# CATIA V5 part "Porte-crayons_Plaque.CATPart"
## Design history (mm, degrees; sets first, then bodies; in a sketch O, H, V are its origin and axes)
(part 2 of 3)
    line L795 (29.2957, 73.0276) -> (29.2344, 72.9847)
    line L796 (29.3535, 73.0745) -> (29.2957, 73.0276)
    line L797 (29.4075, 73.1251) -> (29.3535, 73.0745)
    line L798 (29.4578, 73.1794) -> (29.4075, 73.1251)
    line L799 (29.5043, 73.2373) -> (29.4578, 73.1794)
    line L800 (29.547, 73.2989) -> (29.5043, 73.2373)
    line L801 (29.586, 73.3642) -> (29.547, 73.2989)
    line L802 (29.6213, 73.4331) -> (29.586, 73.3642)
    line L803 (29.6527, 73.5057) -> (29.6213, 73.4331)
    line L804 (29.6804, 73.5819) -> (29.6527, 73.5057)
    line L805 (29.7043, 73.6618) -> (29.6804, 73.5819)
    line L806 (29.2381, 73.7194) -> (29.7043, 73.6618)
    line L807 (24.4786, 72.5574) -> (24.4776, 72.6415)
    line L808 (24.4857, 72.4777) -> (24.4786, 72.5574)
    line L809 (24.4989, 72.4023) -> (24.4857, 72.4777)
    line L810 (24.5181, 72.3313) -> (24.4989, 72.4023)
    line L811 (24.5434, 72.2645) -> (24.5181, 72.3313)
    line L812 (24.5748, 72.2022) -> (24.5434, 72.2645)
    line L813 (24.6122, 72.1441) -> (24.5748, 72.2022)
    line L814 (24.6557, 72.0904) -> (24.6122, 72.1441)
    line L815 (24.7053, 72.041) -> (24.6557, 72.0904)
    line L816 (24.7609, 71.996) -> (24.7053, 72.041)
    line L817 (24.8214, 71.9553) -> (24.7609, 71.996)
    line L818 (24.8855, 71.9188) -> (24.8214, 71.9553)
    line L819 (24.9533, 71.8867) -> (24.8855, 71.9188)
    line L820 (25.0248, 71.8588) -> (24.9533, 71.8867)
    line L821 (25.0999, 71.8352) -> (25.0248, 71.8588)
    line L822 (25.1787, 71.816) -> (25.0999, 71.8352)
    line L823 (25.2612, 71.801) -> (25.1787, 71.816)
    line L824 (25.3473, 71.7902) -> (25.2612, 71.801)
    line L825 (25.4371, 71.7838) -> (25.3473, 71.7902)
    line L826 (25.5305, 71.7817) -> (25.4371, 71.7838)
    line L827 (25.6094, 71.7832) -> (25.5305, 71.7817)
    line L828 (25.6859, 71.7877) -> (25.6094, 71.7832)
    line L829 (25.7597, 71.7952) -> (25.6859, 71.7877)
    line L830 (25.8311, 71.8057) -> (25.7597, 71.7952)
    line L831 (25.8999, 71.8193) -> (25.8311, 71.8057)
    line L832 (25.9662, 71.8358) -> (25.8999, 71.8193)
    line L833 (26.03, 71.8554) -> (25.9662, 71.8358)
    line L834 (26.0912, 71.8779) -> (26.03, 71.8554)
    line L835 (26.1499, 71.9035) -> (26.0912, 71.8779)
    line L836 (26.2061, 71.9321) -> (26.1499, 71.9035)
    line L837 (26.2595, 71.9633) -> (26.2061, 71.9321)
    line L838 (26.3099, 71.9966) -> (26.2595, 71.9633)
    line L839 (26.3575, 72.0321) -> (26.3099, 71.9966)
    line L840 (26.402, 72.0698) -> (26.3575, 72.0321)
    line L841 (26.4436, 72.1097) -> (26.402, 72.0698)
    line L842 (26.4822, 72.1518) -> (26.4436, 72.1097)
    line L843 (26.5179, 72.1961) -> (26.4822, 72.1518)
    line L844 (26.5506, 72.2425) -> (26.5179, 72.1961)
    line L845 (26.5804, 72.2911) -> (26.5506, 72.2425)
    line L846 (26.6072, 72.3419) -> (26.5804, 72.2911)
    line L847 (26.6312, 72.3975) -> (26.6072, 72.3419)
    line L848 (26.6527, 72.4602) -> (26.6312, 72.3975)
    line L849 (26.6717, 72.5302) -> (26.6527, 72.4602)
    line L850 (26.6882, 72.6075) -> (26.6717, 72.5302)
    line L851 (26.7021, 72.692) -> (26.6882, 72.6075)
    line L852 (26.7135, 72.7837) -> (26.7021, 72.692)
    line L853 (26.7224, 72.8827) -> (26.7135, 72.7837)
    line L854 (26.7287, 72.9889) -> (26.7224, 72.8827)
    line L855 (26.7325, 73.1024) -> (26.7287, 72.9889)
    line L856 (26.7338, 73.2231) -> (26.7325, 73.1024)
    line L857 (26.7338, 75.5244) -> (26.7338, 73.2231)
    line L858 (26.3176, 75.5244) -> (26.7338, 75.5244)
    line L859 (26.3176, 75.2035) -> (26.3176, 75.5244)
    line L860 (26.2548, 75.2759) -> (26.3176, 75.2035)
    line L861 (26.1887, 75.3406) -> (26.2548, 75.2759)
    line L862 (26.1192, 75.3978) -> (26.1887, 75.3406)
    line L863 (26.0465, 75.4473) -> (26.1192, 75.3978)
    line L864 (25.9704, 75.4893) -> (26.0465, 75.4473)
    line L865 (25.8911, 75.5236) -> (25.9704, 75.4893)
    line L866 (25.8084, 75.5502) -> (25.8911, 75.5236)
    line L867 (25.7224, 75.5693) -> (25.8084, 75.5502)
    line L868 (25.6331, 75.5807) -> (25.7224, 75.5693)
    line L869 (25.5405, 75.5845) -> (25.6331, 75.5807)
    line L870 (25.4707, 75.5828) -> (25.5405, 75.5845)
    line L871 (25.4028, 75.5775) -> (25.4707, 75.5828)
    line L872 (25.3367, 75.5687) -> (25.4028, 75.5775)
    line L873 (25.2724, 75.5564) -> (25.3367, 75.5687)
    line L874 (25.2099, 75.5407) -> (25.2724, 75.5564)
    line L875 (25.1493, 75.5214) -> (25.2099, 75.5407)
    line L876 (25.0905, 75.4985) -> (25.1493, 75.5214)
    line L877 (25.0335, 75.4722) -> (25.0905, 75.4985)
    line L878 (24.9784, 75.4424) -> (25.0335, 75.4722)
    line L879 (24.9251, 75.409) -> (24.9784, 75.4424)
    line L880 (24.8739, 75.3725) -> (24.9251, 75.409)
    line L881 (24.8253, 75.333) -> (24.8739, 75.3725)
    line L882 (24.7791, 75.2906) -> (24.8253, 75.333)
    line L883 (24.7354, 75.2452) -> (24.7791, 75.2906)
    line L884 (24.6942, 75.1969) -> (24.7354, 75.2452)
    line L885 (24.6554, 75.1457) -> (24.6942, 75.1969)
    line L886 (24.6192, 75.0915) -> (24.6554, 75.1457)
    line L887 (24.5854, 75.0344) -> (24.6192, 75.0915)
    line L888 (24.5541, 74.9744) -> (24.5854, 75.0344)
    line L889 (24.5252, 74.9114) -> (24.5541, 74.9744)
    line L890 (24.4991, 74.8464) -> (24.5252, 74.9114)
    line L891 (24.4756, 74.7802) -> (24.4991, 74.8464)
    line L892 (24.4549, 74.7129) -> (24.4756, 74.7802)
    line L893 (24.437, 74.6443) -> (24.4549, 74.7129)
    line L894 (24.4218, 74.5746) -> (24.437, 74.6443)
    line L895 (24.4094, 74.5037) -> (24.4218, 74.5746)
    line L896 (24.3998, 74.4316) -> (24.4094, 74.5037)
    line L897 (24.3929, 74.3583) -> (24.3998, 74.4316)
    line L898 (24.3888, 74.2839) -> (24.3929, 74.3583)
    line L899 (24.3874, 74.2083) -> (24.3888, 74.2839)
    line L900 (24.3904, 74.099) -> (24.3874, 74.2083)
    line L901 (24.3994, 73.993) -> (24.3904, 74.099)
    line L902 (24.4144, 73.8901) -> (24.3994, 73.993)
    line L903 (24.4355, 73.7903) -> (24.4144, 73.8901)
    line L904 (24.4626, 73.6938) -> (24.4355, 73.7903)
    line L905 (24.4957, 73.6003) -> (24.4626, 73.6938)
    line L906 (24.5348, 73.51) -> (24.4957, 73.6003)
    line L907 (24.5799, 73.4229) -> (24.5348, 73.51)
    line L908 (24.631, 73.339) -> (24.5799, 73.4229)
    line L909 (24.6882, 73.2582) -> (24.631, 73.339)
    line L910 (24.7509, 73.1829) -> (24.6882, 73.2582)
    line L911 (24.8184, 73.1156) -> (24.7509, 73.1829)
    line L912 (24.891, 73.0562) -> (24.8184, 73.1156)
    line L913 (24.9685, 73.0047) -> (24.891, 73.0562)
    line L914 (25.0511, 72.9611) -> (24.9685, 73.0047)
    line L915 (25.1385, 72.9255) -> (25.0511, 72.9611)
    line L916 (25.2309, 72.8978) -> (25.1385, 72.9255)
    line L917 (25.3283, 72.8779) -> (25.2309, 72.8978)
    line L918 (25.4307, 72.8661) -> (25.3283, 72.8779)
    line L919 (25.538, 72.8621) -> (25.4307, 72.8661)
    line L920 (25.6248, 72.8656) -> (25.538, 72.8621)
    line L921 (25.7087, 72.876) -> (25.6248, 72.8656)
    line L922 (25.7896, 72.8935) -> (25.7087, 72.876)
    line L923 (25.8677, 72.9179) -> (25.7896, 72.8935)
    line L924 (25.9429, 72.9492) -> (25.8677, 72.9179)
    line L925 (26.0151, 72.9875) -> (25.9429, 72.9492)
    line L926 (26.0844, 73.0329) -> (26.0151, 72.9875)
    line L927 (26.1509, 73.0851) -> (26.0844, 73.0329)
    line L928 (26.2144, 73.1443) -> (26.1509, 73.0851)
    line L929 (26.275, 73.2105) -> (26.2144, 73.1443)
    line L930 (26.2751, 73.1253) -> (26.275, 73.2105)
    line L931 (26.2745, 73.0462) -> (26.2751, 73.1253)
    line L932 (26.2731, 72.9731) -> (26.2745, 73.0462)
    line L933 (26.271, 72.9061) -> (26.2731, 72.9731)
    line L934 (26.2681, 72.8452) -> (26.271, 72.9061)
    line L935 (26.2645, 72.7903) -> (26.2681, 72.8452)
    line L936 (26.2601, 72.7415) -> (26.2645, 72.7903)
    line L937 (26.2549, 72.6988) -> (26.2601, 72.7415)
    line L938 (26.2491, 72.6621) -> (26.2549, 72.6988)
    line L939 (26.2424, 72.6315) -> (26.2491, 72.6621)
    line L940 (26.2293, 72.5874) -> (26.2424, 72.6315)
    line L941 (26.214, 72.5452) -> (26.2293, 72.5874)
    line L942 (26.1964, 72.5051) -> (26.214, 72.5452)
    line L943 (26.1766, 72.467) -> (26.1964, 72.5051)
    line L944 (26.1547, 72.4309) -> (26.1766, 72.467)
    line L945 (26.1305, 72.3968) -> (26.1547, 72.4309)
    line L946 (26.1042, 72.3648) -> (26.1305, 72.3968)
    line L947 (26.0756, 72.3347) -> (26.1042, 72.3648)
    line L948 (26.0448, 72.3066) -> (26.0756, 72.3347)
    line L949 (26.0118, 72.2805) -> (26.0448, 72.3066)
    line L950 (25.9763, 72.2567) -> (26.0118, 72.2805)
    line L951 (25.9379, 72.2354) -> (25.9763, 72.2567)
    line L952 (25.8967, 72.2166) -> (25.9379, 72.2354)
    line L953 (25.8525, 72.2003) -> (25.8967, 72.2166)
    line L954 (25.8056, 72.1865) -> (25.8525, 72.2003)
    line L955 (25.7558, 72.1752) -> (25.8056, 72.1865)
    line L956 (25.7031, 72.1665) -> (25.7558, 72.1752)
    line L957 (25.6476, 72.1602) -> (25.7031, 72.1665)
    line L958 (25.5892, 72.1564) -> (25.6476, 72.1602)
    line L959 (25.528, 72.1552) -> (25.5892, 72.1564)
    line L960 (25.4711, 72.1564) -> (25.528, 72.1552)
    line L961 (25.4166, 72.1602) -> (25.4711, 72.1564)
    line L962 (25.3646, 72.1665) -> (25.4166, 72.1602)
    line L963 (25.315, 72.1752) -> (25.3646, 72.1665)
    line L964 (25.2679, 72.1865) -> (25.315, 72.1752)
    line L965 (25.2232, 72.2003) -> (25.2679, 72.1865)
    line L966 (25.1811, 72.2166) -> (25.2232, 72.2003)
    line L967 (25.1413, 72.2354) -> (25.1811, 72.2166)
    line L968 (25.104, 72.2567) -> (25.1413, 72.2354)
    line L969 (25.0692, 72.2805) -> (25.104, 72.2567)
    line L970 (25.0451, 72.3002) -> (25.0692, 72.2805)
    line L971 (25.023, 72.322) -> (25.0451, 72.3002)
    line L972 (25.0028, 72.3461) -> (25.023, 72.322)
    line L973 (24.9846, 72.3724) -> (25.0028, 72.3461)
    line L974 (24.9683, 72.4009) -> (24.9846, 72.3724)
    line L975 (24.954, 72.4315) -> (24.9683, 72.4009)
    line L976 (24.9417, 72.4644) -> (24.954, 72.4315)
    line L977 (24.9313, 72.4995) -> (24.9417, 72.4644)
    line L978 (24.9228, 72.5368) -> (24.9313, 72.4995)
    line L979 (24.9163, 72.5763) -> (24.9228, 72.5368)
    line L980 (24.4776, 72.6415) -> (24.9163, 72.5763)
    line L981 (21.5406, 74.0615) -> (21.5371, 74.1932)
    line L982 (21.5509, 73.9361) -> (21.5406, 74.0615)
    line L983 (21.5681, 73.8171) -> (21.5509, 73.9361)
    line L984 (21.5923, 73.7043) -> (21.5681, 73.8171)
    line L985 (21.6233, 73.5979) -> (21.5923, 73.7043)
    line L986 (21.6612, 73.4977) -> (21.6233, 73.5979)
    line L987 (21.706, 73.4039) -> (21.6612, 73.4977)
    line L988 (21.7577, 73.3165) -> (21.706, 73.4039)
    line L989 (21.8163, 73.2353) -> (21.7577, 73.3165)
    line L990 (21.8818, 73.1604) -> (21.8163, 73.2353)
    line L991 (21.9529, 73.0923) -> (21.8818, 73.1604)
    line L992 (22.0283, 73.0314) -> (21.9529, 73.0923)
    line L993 (22.1079, 72.9776) -> (22.0283, 73.0314)
    line L994 (22.1919, 72.931) -> (22.1079, 72.9776)
    line L995 (22.2801, 72.8916) -> (22.1919, 72.931)
    line L996 (22.3726, 72.8593) -> (22.2801, 72.8916)
    line L997 (22.4694, 72.8342) -> (22.3726, 72.8593)
    line L998 (22.5705, 72.8163) -> (22.4694, 72.8342)
    line L999 (22.6759, 72.8055) -> (22.5705, 72.8163)
    line L1000 (22.7855, 72.8019) -> (22.6759, 72.8055)
    line L1001 (22.8547, 72.8036) -> (22.7855, 72.8019)
    line L1002 (22.9227, 72.8085) -> (22.8547, 72.8036)
    line L1003 (22.9897, 72.8166) -> (22.9227, 72.8085)
    line L1004 (23.0557, 72.828) -> (22.9897, 72.8166)
    line L1005 (23.1205, 72.8427) -> (23.0557, 72.828)
    line L1006 (23.1842, 72.8606) -> (23.1205, 72.8427)
    line L1007 (23.2469, 72.8818) -> (23.1842, 72.8606)
    line L1008 (23.3086, 72.9062) -> (23.2469, 72.8818)
    line L1009 (23.3691, 72.9339) -> (23.3086, 72.9062)
    line L1010 (23.4285, 72.9649) -> (23.3691, 72.9339)
    line L1011 (23.486, 72.9988) -> (23.4285, 72.9649)
    line L1012 (23.5407, 73.0353) -> (23.486, 72.9988)
    line L1013 (23.5926, 73.0745) -> (23.5407, 73.0353)
    line L1014 (23.6417, 73.1163) -> (23.5926, 73.0745)
    line L1015 (23.688, 73.1607) -> (23.6417, 73.1163)
    line L1016 (23.7314, 73.2078) -> (23.688, 73.1607)
    line L1017 (23.7721, 73.2575) -> (23.7314, 73.2078)
    line L1018 (23.81, 73.3098) -> (23.7721, 73.2575)
    line L1019 (23.845, 73.3648) -> (23.81, 73.3098)
    line L1020 (23.8772, 73.4224) -> (23.845, 73.3648)
    line L1021 (23.9065, 73.4835) -> (23.8772, 73.4224)
    line L1022 (23.9327, 73.549) -> (23.9065, 73.4835)
    line L1023 (23.9559, 73.6189) -> (23.9327, 73.549)
    line L1024 (23.9759, 73.6931) -> (23.9559, 73.6189)
    line L1025 (23.9929, 73.7718) -> (23.9759, 73.6931)
    line L1026 (24.0067, 73.8548) -> (23.9929, 73.7718)
    line L1027 (24.0175, 73.9422) -> (24.0067, 73.8548)
    line L1028 (24.0252, 74.0341) -> (24.0175, 73.9422)
    line L1029 (24.0299, 74.1302) -> (24.0252, 74.0341)
    line L1030 (24.0314, 74.2308) -> (24.0299, 74.1302)
    line L1031 (24.0279, 74.3549) -> (24.0314, 74.2308)
    line L1032 (24.0175, 74.4735) -> (24.0279, 74.3549)
    line L1033 (24, 74.5867) -> (24.0175, 74.4735)
    line L1034 (23.9757, 74.6943) -> (24, 74.5867)
    line L1035 (23.9443, 74.7964) -> (23.9757, 74.6943)
    line L1036 (23.906, 74.8931) -> (23.9443, 74.7964)
    line L1037 (23.8607, 74.9842) -> (23.906, 74.8931)
    line L1038 (23.8084, 75.0699) -> (23.8607, 74.9842)
    line L1039 (23.7492, 75.1501) -> (23.8084, 75.0699)
    line L1040 (23.683, 75.2248) -> (23.7492, 75.1501)
    line L1041 (23.6113, 75.2931) -> (23.683, 75.2248)
    line L1042 (23.5356, 75.3543) -> (23.6113, 75.2931)
    line L1043 (23.4558, 75.4082) -> (23.5356, 75.3543)
    line L1044 (23.3721, 75.455) -> (23.4558, 75.4082)
    line L1045 (23.2844, 75.4946) -> (23.3721, 75.455)
    line L1046 (23.1926, 75.5269) -> (23.2844, 75.4946)
    line L1047 (23.0969, 75.5521) -> (23.1926, 75.5269)
    line L1048 (22.9971, 75.5701) -> (23.0969, 75.5521)
    line L1049 (22.8933, 75.5809) -> (22.9971, 75.5701)
    line L1050 (22.7855, 75.5845) -> (22.8933, 75.5809)
    line L1051 (22.6883, 75.5816) -> (22.7855, 75.5845)
    line L1052 (22.594, 75.5727) -> (22.6883, 75.5816)
    line L1053 (22.5027, 75.5579) -> (22.594, 75.5727)
    line L1054 (22.4145, 75.5372) -> (22.5027, 75.5579)
    line L1055 (22.3293, 75.5106) -> (22.4145, 75.5372)
    line L1056 (22.247, 75.478) -> (22.3293, 75.5106)
    line L1057 (22.1678, 75.4396) -> (22.247, 75.478)
    line L1058 (22.0916, 75.3952) -> (22.1678, 75.4396)
    line L1059 (22.0184, 75.3449) -> (22.0916, 75.3952)
    line L1060 (21.9482, 75.2887) -> (22.0184, 75.3449)
    line L1061 (21.8701, 75.2137) -> (21.9482, 75.2887)
    line L1062 (21.8002, 75.131) -> (21.8701, 75.2137)
    line L1063 (21.7386, 75.0406) -> (21.8002, 75.131)
    line L1064 (21.6851, 74.9426) -> (21.7386, 75.0406)
    line L1065 (21.6399, 74.8368) -> (21.6851, 74.9426)
    line L1066 (21.6029, 74.7235) -> (21.6399, 74.8368)
    line L1067 (21.5741, 74.6024) -> (21.6029, 74.7235)
    line L1068 (21.5536, 74.4737) -> (21.5741, 74.6024)
    line L1069 (21.5412, 74.3373) -> (21.5536, 74.4737)
    line L1070 (21.5371, 74.1932) -> (21.5412, 74.3373)
    line L1071 (17.8797, 72.8621) -> (17.4284, 72.8621)
    line L1072 (17.8797, 74.2434) -> (17.8797, 72.8621)
    line L1073 (17.8804, 74.3144) -> (17.8797, 74.2434)
    line L1074 (17.8826, 74.3819) -> (17.8804, 74.3144)
    line L1075 (17.8862, 74.4461) -> (17.8826, 74.3819)
    line L1076 (17.8913, 74.5069) -> (17.8862, 74.4461)
    line L1077 (17.8978, 74.5642) -> (17.8913, 74.5069)
    line L1078 (17.9058, 74.6182) -> (17.8978, 74.5642)
    line L1079 (17.9153, 74.6687) -> (17.9058, 74.6182)
    line L1080 (17.9262, 74.7159) -> (17.9153, 74.6687)
    line L1081 (17.9385, 74.7596) -> (17.9262, 74.7159)
    line L1082 (17.9523, 74.7999) -> (17.9385, 74.7596)
    line L1083 (17.9678, 74.8376) -> (17.9523, 74.7999)
    line L1084 (17.985, 74.8734) -> (17.9678, 74.8376)
    line L1085 (18.004, 74.9073) -> (17.985, 74.8734)
    line L1086 (18.0248, 74.9395) -> (18.004, 74.9073)
    line L1087 (18.0473, 74.9697) -> (18.0248, 74.9395)
    line L1088 (18.0716, 74.9981) -> (18.0473, 74.9697)
    line L1089 (18.0977, 75.0247) -> (18.0716, 74.9981)
    line L1090 (18.1256, 75.0494) -> (18.0977, 75.0247)
    line L1091 (18.1553, 75.0722) -> (18.1256, 75.0494)
    line L1092 (18.1867, 75.0932) -> (18.1553, 75.0722)
    line L1093 (18.2194, 75.1122) -> (18.1867, 75.0932)
    line L1094 (18.2526, 75.1293) -> (18.2194, 75.1122)
    line L1095 (18.2864, 75.1443) -> (18.2526, 75.1293)
    line L1096 (18.3207, 75.1573) -> (18.2864, 75.1443)
    line L1097 (18.3556, 75.1684) -> (18.3207, 75.1573)
    line L1098 (18.3912, 75.1774) -> (18.3556, 75.1684)
    line L1099 (18.4272, 75.1844) -> (18.3912, 75.1774)
    line L1100 (18.4639, 75.1894) -> (18.4272, 75.1844)
    line L1101 (18.5011, 75.1924) -> (18.4639, 75.1894)
    line L1102 (18.539, 75.1934) -> (18.5011, 75.1924)
    line L1103 (18.5877, 75.1919) -> (18.539, 75.1934)
    line L1104 (18.6336, 75.1874) -> (18.5877, 75.1919)
    line L1105 (18.6767, 75.1799) -> (18.6336, 75.1874)
    line L1106 (18.717, 75.1694) -> (18.6767, 75.1799)
    line L1107 (18.7545, 75.1558) -> (18.717, 75.1694)
    line L1108 (18.7892, 75.1393) -> (18.7545, 75.1558)
    line L1109 (18.8211, 75.1197) -> (18.7892, 75.1393)
    line L1110 (18.8502, 75.0972) -> (18.8211, 75.1197)
    line L1111 (18.8765, 75.0716) -> (18.8502, 75.0972)
    line L1112 (18.8999, 75.043) -> (18.8765, 75.0716)
    line L1113 (18.9209, 75.0115) -> (18.8999, 75.043)
    line L1114 (18.9397, 74.9769) -> (18.9209, 75.0115)
    line L1115 (18.9562, 74.9393) -> (18.9397, 74.9769)
    line L1116 (18.9705, 74.8986) -> (18.9562, 74.9393)
    line L1117 (18.9827, 74.855) -> (18.9705, 74.8986)
    line L1118 (18.9926, 74.8084) -> (18.9827, 74.855)
    line L1119 (19.0003, 74.7588) -> (18.9926, 74.8084)
    line L1120 (19.0058, 74.7061) -> (19.0003, 74.7588)
    line L1121 (19.0091, 74.6505) -> (19.0058, 74.7061)
    line L1122 (19.0102, 74.5918) -> (19.0091, 74.6505)
    line L1123 (19.0102, 72.8621) -> (19.0102, 74.5918)
    line L1124 (19.4615, 72.8621) -> (19.0102, 72.8621)
    line L1125 (19.4615, 74.4088) -> (19.4615, 72.8621)
    line L1126 (19.4633, 74.4888) -> (19.4615, 74.4088)
    line L1127 (19.4689, 74.5643) -> (19.4633, 74.4888)
    line L1128 (19.4782, 74.6353) -> (19.4689, 74.5643)
    line L1129 (19.4911, 74.7018) -> (19.4782, 74.6353)
    line L1130 (19.5079, 74.7638) -> (19.4911, 74.7018)
    line L1131 (19.5282, 74.8214) -> (19.5079, 74.7638)
    line L1132 (19.5524, 74.8745) -> (19.5282, 74.8214)
    line L1133 (19.5802, 74.923) -> (19.5524, 74.8745)
    line L1134 (19.6117, 74.9671) -> (19.5802, 74.923)
    line L1135 (19.647, 75.0067) -> (19.6117, 74.9671)
    line L1136 (19.685, 75.0422) -> (19.647, 75.0067)
    line L1137 (19.725, 75.0739) -> (19.685, 75.0422)
    line L1138 (19.7669, 75.1019) -> (19.725, 75.0739)
    line L1139 (19.8106, 75.1262) -> (19.7669, 75.1019)
    line L1140 (19.8563, 75.1468) -> (19.8106, 75.1262)
    line L1141 (19.9039, 75.1636) -> (19.8563, 75.1468)
    line L1142 (19.9534, 75.1766) -> (19.9039, 75.1636)
    line L1143 (20.0047, 75.186) -> (19.9534, 75.1766)
    line L1144 (20.058, 75.1916) -> (20.0047, 75.186)
    line L1145 (20.1132, 75.1934) -> (20.058, 75.1916)
    line L1146 (20.1439, 75.1927) -> (20.1132, 75.1934)
    line L1147 (20.1738, 75.1905) -> (20.1439, 75.1927)
    line L1148 (20.2029, 75.1869) -> (20.1738, 75.1905)
    line L1149 (20.2312, 75.1818) -> (20.2029, 75.1869)
    line L1150 (20.2586, 75.1753) -> (20.2312, 75.1818)
    line L1151 (20.2853, 75.1673) -> (20.2586, 75.1753)
    line L1152 (20.3112, 75.1578) -> (20.2853, 75.1673)
    line L1153 (20.3362, 75.1469) -> (20.3112, 75.1578)
    line L1154 (20.3605, 75.1346) -> (20.3362, 75.1469)
    line L1155 (20.384, 75.1208) -> (20.3605, 75.1346)
    line L1156 (20.4063, 75.1057) -> (20.384, 75.1208)
    line L1157 (20.4272, 75.0898) -> (20.4063, 75.1057)
    line L1158 (20.4468, 75.073) -> (20.4272, 75.0898)
    line L1159 (20.4648, 75.0552) -> (20.4468, 75.073)
    line L1160 (20.4814, 75.0365) -> (20.4648, 75.0552)
    line L1161 (20.4966, 75.0168) -> (20.4814, 75.0365)
    line L1162 (20.5104, 74.9962) -> (20.4966, 75.0168)
    line L1163 (20.5228, 74.9747) -> (20.5104, 74.9962)
    line L1164 (20.5337, 74.9523) -> (20.5228, 74.9747)
    line L1165 (20.5432, 74.929) -> (20.5337, 74.9523)
    line L1166 (20.5515, 74.9036) -> (20.5432, 74.929)
    line L1167 (20.5589, 74.8753) -> (20.5515, 74.9036)
    line L1168 (20.5655, 74.8439) -> (20.5589, 74.8753)
    line L1169 (20.5712, 74.8094) -> (20.5655, 74.8439)
    line L1170 (20.5761, 74.772) -> (20.5712, 74.8094)
    line L1171 (20.58, 74.7315) -> (20.5761, 74.772)
    line L1172 (20.5831, 74.688) -> (20.58, 74.7315)
    line L1173 (20.5853, 74.6414) -> (20.5831, 74.688)
    line L1174 (20.5866, 74.5918) -> (20.5853, 74.6414)
    line L1175 (20.587, 74.5392) -> (20.5866, 74.5918)
    line L1176 (20.587, 72.8621) -> (20.587, 74.5392)
    line L1177 (21.0358, 72.8621) -> (20.587, 72.8621)
    line L1178 (21.0358, 74.6896) -> (21.0358, 72.8621)
    line L1179 (21.0336, 74.7785) -> (21.0358, 74.6896)
    line L1180 (21.0272, 74.8626) -> (21.0336, 74.7785)
    line L1181 (21.0166, 74.942) -> (21.0272, 74.8626)
    line L1182 (21.0017, 75.0167) -> (21.0166, 74.942)
    line L1183 (20.9825, 75.0866) -> (21.0017, 75.0167)
    line L1184 (20.959, 75.1518) -> (20.9825, 75.0866)
    line L1185 (20.9313, 75.2122) -> (20.959, 75.1518)
    line L1186 (20.8994, 75.2679) -> (20.9313, 75.2122)
    line L1187 (20.8632, 75.3189) -> (20.8994, 75.2679)
    line L1188 (20.8227, 75.3652) -> (20.8632, 75.3189)
    line L1189 (20.7782, 75.4068) -> (20.8227, 75.3652)
    line L1190 (20.7301, 75.4441) -> (20.7782, 75.4068)
    line L1191 (20.6784, 75.477) -> (20.7301, 75.4441)
    line L1192 (20.6229, 75.5055) -> (20.6784, 75.477)
    line L1193 (20.5638, 75.5297) -> (20.6229, 75.5055)
    line L1194 (20.5011, 75.5494) -> (20.5638, 75.5297)
    line L1195 (20.4347, 75.5648) -> (20.5011, 75.5494)
    line L1196 (20.3646, 75.5757) -> (20.4347, 75.5648)
    line L1197 (20.2909, 75.5823) -> (20.3646, 75.5757)
    line L1198 (20.2135, 75.5845) -> (20.2909, 75.5823)
    line L1199 (20.1141, 75.5799) -> (20.2135, 75.5845)
    line L1200 (20.0186, 75.5659) -> (20.1141, 75.5799)
    line L1201 (19.9268, 75.5426) -> (20.0186, 75.5659)
    line L1202 (19.8389, 75.5099) -> (19.9268, 75.5426)
    line L1203 (19.7548, 75.4679) -> (19.8389, 75.5099)
    line L1204 (19.6745, 75.4167) -> (19.7548, 75.4679)
    line L1205 (19.5979, 75.3561) -> (19.6745, 75.4167)
    line L1206 (19.5252, 75.2861) -> (19.5979, 75.3561)
    line L1207 (19.4564, 75.2068) -> (19.5252, 75.2861)
    line L1208 (19.3913, 75.1182) -> (19.4564, 75.2068)
    line L1209 (19.3746, 75.1614) -> (19.3913, 75.1182)
    line L1210 (19.3557, 75.2026) -> (19.3746, 75.1614)
    line L1211 (19.3346, 75.2418) -> (19.3557, 75.2026)
    line L1212 (19.3113, 75.2791) -> (19.3346, 75.2418)
    line L1213 (19.2857, 75.3144) -> (19.3113, 75.2791)
    line L1214 (19.2579, 75.3478) -> (19.2857, 75.3144)
    line L1215 (19.2278, 75.3792) -> (19.2579, 75.3478)
    line L1216 (19.1955, 75.4086) -> (19.2278, 75.3792)
    line L1217 (19.161, 75.4361) -> (19.1955, 75.4086)
    line L1218 (19.1243, 75.4617) -> (19.161, 75.4361)
    line L1219 (19.0854, 75.485) -> (19.1243, 75.4617)
    line L1220 (19.0443, 75.5059) -> (19.0854, 75.485)
    line L1221 (19.0012, 75.5243) -> (19.0443, 75.5059)
    line L1222 (18.9558, 75.5403) -> (19.0012, 75.5243)
    line L1223 (18.9084, 75.5538) -> (18.9558, 75.5403)
    line L1224 (18.8588, 75.5649) -> (18.9084, 75.5538)
    line L1225 (18.8071, 75.5735) -> (18.8588, 75.5649)
    line L1226 (18.7533, 75.5796) -> (18.8071, 75.5735)
    line L1227 (18.6973, 75.5833) -> (18.7533, 75.5796)
    line L1228 (18.6392, 75.5845) -> (18.6973, 75.5833)
    line L1229 (18.5867, 75.5833) -> (18.6392, 75.5845)
    line L1230 (18.5352, 75.5797) -> (18.5867, 75.5833)
    line L1231 (18.485, 75.5738) -> (18.5352, 75.5797)
    line L1232 (18.4359, 75.5655) -> (18.485, 75.5738)
    line L1233 (18.3879, 75.5548) -> (18.4359, 75.5655)
    line L1234 (18.3411, 75.5416) -> (18.3879, 75.5548)
    line L1235 (18.2955, 75.5262) -> (18.3411, 75.5416)
    line L1236 (18.251, 75.5083) -> (18.2955, 75.5262)
    line L1237 (18.2076, 75.4881) -> (18.251, 75.5083)
    line L1238 (18.1654, 75.4654) -> (18.2076, 75.4881)
    line L1239 (18.1247, 75.4409) -> (18.1654, 75.4654)
    line L1240 (18.0855, 75.4147) -> (18.1247, 75.4409)
    line L1241 (18.048, 75.3871) -> (18.0855, 75.4147)
    line L1242 (18.0122, 75.358) -> (18.048, 75.3871)
    line L1243 (17.9781, 75.3273) -> (18.0122, 75.358)
    line L1244 (17.9456, 75.295) -> (17.9781, 75.3273)
    line L1245 (17.9147, 75.2613) -> (17.9456, 75.295)
    line L1246 (17.8855, 75.226) -> (17.9147, 75.2613)
    line L1247 (17.8579, 75.1892) -> (17.8855, 75.226)
    line L1248 (17.832, 75.1508) -> (17.8579, 75.1892)
    line L1249 (17.832, 75.5244) -> (17.832, 75.1508)
    line L1250 (17.4284, 75.5244) -> (17.832, 75.5244)
    line L1251 (17.4284, 72.8621) -> (17.4284, 75.5244)
    line L1252 (16.7416, 72.8621) -> (16.2903, 72.8621)
    line L1253 (16.7416, 75.5244) -> (16.7416, 72.8621)
    line L1254 (16.2903, 75.5244) -> (16.7416, 75.5244)
    line L1255 (16.2903, 72.8621) -> (16.2903, 75.5244)
    line L1256 (16.7416, 76.0182) -> (16.2903, 76.0182)
    line L1257 (16.7416, 76.5371) -> (16.7416, 76.0182)
    line L1258 (16.2903, 76.5371) -> (16.7416, 76.5371)
    line L1259 (16.2903, 76.0182) -> (16.2903, 76.5371)
    line L1260 (15.7664, 72.8621) -> (13.4702, 72.8621)
    line L1261 (15.7664, 73.2958) -> (15.7664, 72.8621)
    line L1262 (13.9565, 73.2958) -> (15.7664, 73.2958)
    line L1263 (13.9565, 76.5371) -> (13.9565, 73.2958)
    line L1264 (13.4702, 76.5371) -> (13.9565, 76.5371)
    line L1265 (13.4702, 72.8621) -> (13.4702, 76.5371)
    line L1266 (35.2582, 88.4202) -> (32.1239, 88.4202)
    line L1267 (35.2582, 88.9158) -> (35.2582, 88.4202)
    line L1268 (32.6798, 88.9158) -> (35.2582, 88.9158)
    line L1269 (32.6798, 90.3454) -> (32.6798, 88.9158)
    line L1270 (35.0032, 90.3454) -> (32.6798, 90.3454)
    line L1271 (35.0032, 90.8382) -> (35.0032, 90.3454)
    line L1272 (32.6798, 90.8382) -> (35.0032, 90.8382)
    line L1273 (32.6798, 92.1245) -> (32.6798, 90.8382)
    line L1274 (35.1608, 92.1245) -> (32.6798, 92.1245)
    line L1275 (35.1608, 92.6202) -> (35.1608, 92.1245)
    line L1276 (32.1239, 92.6202) -> (35.1608, 92.6202)
    line L1277 (32.1239, 88.4202) -> (32.1239, 92.6202)
    line L1278 (29.7833, 92.878) -> (29.3564, 92.878)
    line L1279 (30.4136, 93.6802) -> (29.7833, 92.878)
    line L1280 (29.7375, 93.6802) -> (30.4136, 93.6802)
    line L1281 (29.3564, 92.878) -> (29.7375, 93.6802)
    line L1282 (31.3447, 88.4202) -> (28.2104, 88.4202)
    line L1283 (31.3447, 88.9158) -> (31.3447, 88.4202)
    line L1284 (28.7662, 88.9158) -> (31.3447, 88.9158)
    line L1285 (28.7662, 90.3454) -> (28.7662, 88.9158)
    line L1286 (31.0897, 90.3454) -> (28.7662, 90.3454)
    line L1287 (31.0897, 90.8382) -> (31.0897, 90.3454)
    line L1288 (28.7662, 90.8382) -> (31.0897, 90.8382)
    line L1289 (28.7662, 92.1245) -> (28.7662, 90.8382)
    line L1290 (31.2473, 92.1245) -> (28.7662, 92.1245)
    line L1291 (31.2473, 92.6202) -> (31.2473, 92.1245)
    line L1292 (28.2104, 92.6202) -> (31.2473, 92.6202)
    line L1293 (28.2104, 88.4202) -> (28.2104, 92.6202)
    line L1294 (26.9334, 89.7894) -> (26.9585, 89.8927)
    line L1295 (26.9042, 89.6912) -> (26.9334, 89.7894)
    line L1296 (26.8709, 89.5982) -> (26.9042, 89.6912)
    line L1297 (26.8333, 89.5104) -> (26.8709, 89.5982)
    line L1298 (26.7916, 89.4279) -> (26.8333, 89.5104)
    line L1299 (26.7456, 89.3506) -> (26.7916, 89.4279)
    line L1300 (26.6955, 89.2785) -> (26.7456, 89.3506)
    line L1301 (26.6413, 89.2116) -> (26.6955, 89.2785)
    line L1302 (26.5828, 89.1499) -> (26.6413, 89.2116)
    line L1303 (26.5201, 89.0934) -> (26.5828, 89.1499)
    line L1304 (26.4539, 89.0423) -> (26.5201, 89.0934)
    line L1305 (26.3849, 88.9965) -> (26.4539, 89.0423)
    line L1306 (26.313, 88.9561) -> (26.3849, 88.9965)
    line L1307 (26.2382, 88.9211) -> (26.313, 88.9561)
    line L1308 (26.1606, 88.8914) -> (26.2382, 88.9211)
    line L1309 (26.0801, 88.8672) -> (26.1606, 88.8914)
    line L1310 (25.9967, 88.8484) -> (26.0801, 88.8672)
    line L1311 (25.9105, 88.8349) -> (25.9967, 88.8484)
    line L1312 (25.8214, 88.8268) -> (25.9105, 88.8349)
    line L1313 (25.7294, 88.8241) -> (25.8214, 88.8268)
    line L1314 (25.6532, 88.8261) -> (25.7294, 88.8241)
    line L1315 (25.578, 88.832) -> (25.6532, 88.8261)
    line L1316 (25.504, 88.8419) -> (25.578, 88.832)
    line L1317 (25.431, 88.8557) -> (25.504, 88.8419)
    line L1318 (25.3591, 88.8735) -> (25.431, 88.8557)
    line L1319 (25.2883, 88.8953) -> (25.3591, 88.8735)
    line L1320 (25.2186, 88.921) -> (25.2883, 88.8953)
    line L1321 (25.15, 88.9506) -> (25.2186, 88.921)
    line L1322 (25.0825, 88.9842) -> (25.15, 88.9506)
    line L1323 (25.016, 89.0218) -> (25.0825, 88.9842)
    line L1324 (24.9519, 89.0634) -> (25.016, 89.0218)
    line L1325 (24.8912, 89.1089) -> (24.9519, 89.0634)
    line L1326 (24.834, 89.1586) -> (24.8912, 89.1089)
    line L1327 (24.7802, 89.2122) -> (24.834, 89.1586)
    line L1328 (24.7299, 89.27) -> (24.7802, 89.2122)
    line L1329 (24.6831, 89.3317) -> (24.7299, 89.27)
    line L1330 (24.6397, 89.3975) -> (24.6831, 89.3317)
    line L1331 (24.5998, 89.4673) -> (24.6397, 89.3975)
    line L1332 (24.5634, 89.5412) -> (24.5998, 89.4673)
    line L1333 (24.5304, 89.6191) -> (24.5634, 89.5412)
    line L1334 (24.5008, 89.7004) -> (24.5304, 89.6191)
    line L1335 (24.4742, 89.7844) -> (24.5008, 89.7004)
    line L1336 (24.4508, 89.8712) -> (24.4742, 89.7844)
    line L1337 (24.4305, 89.9606) -> (24.4508, 89.8712)
    line L1338 (24.4133, 90.0528) -> (24.4305, 89.9606)
    line L1339 (24.3993, 90.1477) -> (24.4133, 90.0528)
    line L1340 (24.3883, 90.2453) -> (24.3993, 90.1477)
    line L1341 (24.3805, 90.3457) -> (24.3883, 90.2453)
    line L1342 (24.3759, 90.4487) -> (24.3805, 90.3457)
    line L1343 (24.3743, 90.5545) -> (24.3759, 90.4487)
    line L1344 (24.3756, 90.6374) -> (24.3743, 90.5545)
    line L1345 (24.3796, 90.7197) -> (24.3756, 90.6374)
    line L1346 (24.3861, 90.8016) -> (24.3796, 90.7197)
    line L1347 (24.3954, 90.883) -> (24.3861, 90.8016)
    line L1348 (24.4072, 90.9639) -> (24.3954, 90.883)
    line L1349 (24.4217, 91.0443) -> (24.4072, 90.9639)
    line L1350 (24.4389, 91.1242) -> (24.4217, 91.0443)
    line L1351 (24.4586, 91.2036) -> (24.4389, 91.1242)
    line L1352 (24.481, 91.2826) -> (24.4586, 91.2036)
    line L1353 (24.5061, 91.361) -> (24.481, 91.2826)
    line L1354 (24.5344, 91.4376) -> (24.5061, 91.361)
    line L1355 (24.5665, 91.5111) -> (24.5344, 91.4376)
    line L1356 (24.6026, 91.5813) -> (24.5665, 91.5111)
    line L1357 (24.6424, 91.6484) -> (24.6026, 91.5813)
    line L1358 (24.6862, 91.7123) -> (24.6424, 91.6484)
    line L1359 (24.7338, 91.773) -> (24.6862, 91.7123)
    line L1360 (24.7853, 91.8306) -> (24.7338, 91.773)
    line L1361 (24.8407, 91.8849) -> (24.7853, 91.8306)
    line L1362 (24.8999, 91.9361) -> (24.8407, 91.8849)
    line L1363 (24.963, 91.9841) -> (24.8999, 91.9361)
    line L1364 (25.0297, 92.0282) -> (24.963, 91.9841)
    line L1365 (25.0995, 92.0677) -> (25.0297, 92.0282)
    line L1366 (25.1724, 92.1025) -> (25.0995, 92.0677)
    line L1367 (25.2486, 92.1327) -> (25.1724, 92.1025)
    line L1368 (25.328, 92.1582) -> (25.2486, 92.1327)
    line L1369 (25.4105, 92.1791) -> (25.328, 92.1582)
    line L1370 (25.4962, 92.1953) -> (25.4105, 92.1791)
    line L1371 (25.5851, 92.2069) -> (25.4962, 92.1953)
    line L1372 (25.6771, 92.2139) -> (25.5851, 92.2069)
    line L1373 (25.7724, 92.2162) -> (25.6771, 92.2139)
    line L1374 (25.8552, 92.2141) -> (25.7724, 92.2162)
    line L1375 (25.9351, 92.2078) -> (25.8552, 92.2141)
    line L1376 (26.0122, 92.1974) -> (25.9351, 92.2078)
    line L1377 (26.0864, 92.1827) -> (26.0122, 92.1974)
    line L1378 (26.1577, 92.1639) -> (26.0864, 92.1827)
    line L1379 (26.2262, 92.1409) -> (26.1577, 92.1639)
    line L1380 (26.2918, 92.1137) -> (26.2262, 92.1409)
    line L1381 (26.3545, 92.0824) -> (26.2918, 92.1137)
    line L1382 (26.4144, 92.0468) -> (26.3545, 92.0824)
    line L1383 (26.4714, 92.0071) -> (26.4144, 92.0468)
    line L1384 (26.5257, 91.9627) -> (26.4714, 92.0071)
    line L1385 (26.5773, 91.9134) -> (26.5257, 91.9627)
    line L1386 (26.6263, 91.8592) -> (26.5773, 91.9134)
    line L1387 (26.6727, 91.7999) -> (26.6263, 91.8592)
    line L1388 (26.7164, 91.7356) -> (26.6727, 91.7999)
    line L1389 (26.7575, 91.6664) -> (26.7164, 91.7356)
    line L1390 (26.7959, 91.5921) -> (26.7575, 91.6664)
    line L1391 (26.8317, 91.5129) -> (26.7959, 91.5921)
    line L1392 (26.8649, 91.4287) -> (26.8317, 91.5129)
    line L1393 (26.8954, 91.3395) -> (26.8649, 91.4287)
    line L1394 (27.4426, 91.4685) -> (26.8954, 91.3395)
    line L1395 (27.4062, 91.5822) -> (27.4426, 91.4685)
    line L1396 (27.3646, 91.6907) -> (27.4062, 91.5822)
    line L1397 (27.3177, 91.7939) -> (27.3646, 91.6907)
    line L1398 (27.2657, 91.892) -> (27.3177, 91.7939)
    line L1399 (27.2084, 91.9849) -> (27.2657, 91.892)
    line L1400 (27.1459, 92.0725) -> (27.2084, 91.9849)
    line L1401 (27.0782, 92.1549) -> (27.1459, 92.0725)
    line L1402 (27.0053, 92.2321) -> (27.0782, 92.1549)
    line L1403 (26.9272, 92.3041) -> (27.0053, 92.2321)
    line L1404 (26.8439, 92.3709) -> (26.9272, 92.3041)
    line L1405 (26.7559, 92.4319) -> (26.8439, 92.3709)
    line L1406 (26.6639, 92.4864) -> (26.7559, 92.4319)
    line L1407 (26.568, 92.5346) -> (26.6639, 92.4864)
    line L1408 (26.468, 92.5763) -> (26.568, 92.5346)
    line L1409 (26.364, 92.6116) -> (26.468, 92.5763)
    line L1410 (26.256, 92.6404) -> (26.364, 92.6116)
    line L1411 (26.144, 92.6629) -> (26.256, 92.6404)
    line L1412 (26.0279, 92.679) -> (26.144, 92.6629)
    line L1413 (25.9079, 92.6886) -> (26.0279, 92.679)
    line L1414 (25.7838, 92.6918) -> (25.9079, 92.6886)
    line L1415 (25.6736, 92.6892) -> (25.7838, 92.6918)
    line L1416 (25.5652, 92.6816) -> (25.6736, 92.6892)
    line L1417 (25.4587, 92.6689) -> (25.5652, 92.6816)
    line L1418 (25.3541, 92.6512) -> (25.4587, 92.6689)
    line L1419 (25.2513, 92.6284) -> (25.3541, 92.6512)
    line L1420 (25.1504, 92.6005) -> (25.2513, 92.6284)
    line L1421 (25.0513, 92.5675) -> (25.1504, 92.6005)
    line L1422 (24.9541, 92.5295) -> (25.0513, 92.5675)
    line L1423 (24.8588, 92.4864) -> (24.9541, 92.5295)
    line L1424 (24.7653, 92.4382) -> (24.8588, 92.4864)
    line L1425 (24.6749, 92.3852) -> (24.7653, 92.4382)
    line L1426 (24.5888, 92.3274) -> (24.6749, 92.3852)
    line L1427 (24.5068, 92.265) -> (24.5888, 92.3274)
    line L1428 (24.4291, 92.1978) -> (24.5068, 92.265)
    line L1429 (24.3557, 92.1259) -> (24.4291, 92.1978)
    line L1430 (24.2864, 92.0494) -> (24.3557, 92.1259)
    line L1431 (24.2215, 91.9681) -> (24.2864, 92.0494)
    line L1432 (24.1607, 91.8822) -> (24.2215, 91.9681)
    line L1433 (24.1042, 91.7916) -> (24.1607, 91.8822)
    line L1434 (24.052, 91.6962) -> (24.1042, 91.7916)
    line L1435 (24.0044, 91.5968) -> (24.052, 91.6962)
    line L1436 (23.9617, 91.4941) -> (24.0044, 91.5968)
    line L1437 (23.9241, 91.388) -> (23.9617, 91.4941)
    line L1438 (23.8915, 91.2786) -> (23.9241, 91.388)
    line L1439 (23.864, 91.1658) -> (23.8915, 91.2786)
    line L1440 (23.8414, 91.0497) -> (23.864, 91.1658)
    line L1441 (23.8239, 90.9302) -> (23.8414, 91.0497)
    line L1442 (23.8113, 90.8074) -> (23.8239, 90.9302)
    line L1443 (23.8038, 90.6812) -> (23.8113, 90.8074)
    line L1444 (23.8013, 90.5517) -> (23.8038, 90.6812)
    line L1445 (23.8035, 90.4321) -> (23.8013, 90.5517)
    line L1446 (23.8102, 90.3141) -> (23.8035, 90.4321)
    line L1447 (23.8213, 90.1977) -> (23.8102, 90.3141)
    line L1448 (23.8368, 90.0827) -> (23.8213, 90.1977)
    line L1449 (23.8568, 89.9694) -> (23.8368, 90.0827)
    line L1450 (23.8812, 89.8576) -> (23.8568, 89.9694)
    line L1451 (23.9101, 89.7473) -> (23.8812, 89.8576)
    line L1452 (23.9434, 89.6386) -> (23.9101, 89.7473)
    line L1453 (23.9811, 89.5314) -> (23.9434, 89.6386)
    line L1454 (24.0233, 89.4258) -> (23.9811, 89.5314)
    line L1455 (24.0698, 89.3234) -> (24.0233, 89.4258)
    line L1456 (24.1203, 89.2259) -> (24.0698, 89.3234)
    line L1457 (24.1748, 89.1335) -> (24.1203, 89.2259)
    line L1458 (24.2335, 89.046) -> (24.1748, 89.1335)
    line L1459 (24.2962, 88.9634) -> (24.2335, 89.046)
    line L1460 (24.363, 88.8858) -> (24.2962, 88.9634)
    line L1461 (24.4338, 88.8132) -> (24.363, 88.8858)
    line L1462 (24.5088, 88.7455) -> (24.4338, 88.8132)
    line L1463 (24.5877, 88.6828) -> (24.5088, 88.7455)
    line L1464 (24.6708, 88.625) -> (24.5877, 88.6828)
    line L1465 (24.7584, 88.5725) -> (24.6708, 88.625)
    line L1466 (24.8511, 88.5255) -> (24.7584, 88.5725)
    line L1467 (24.9489, 88.484) -> (24.8511, 88.5255)
    line L1468 (25.0517, 88.4481) -> (24.9489, 88.484)
    line L1469 (25.1596, 88.4176) -> (25.0517, 88.4481)
    line L1470 (25.2726, 88.3928) -> (25.1596, 88.4176)
    line L1471 (25.3907, 88.3734) -> (25.2726, 88.3928)
    line L1472 (25.5138, 88.3596) -> (25.3907, 88.3734)
    line L1473 (25.642, 88.3513) -> (25.5138, 88.3596)
    line L1474 (25.7752, 88.3485) -> (25.642, 88.3513)
    line L1475 (25.9044, 88.3521) -> (25.7752, 88.3485)
    line L1476 (26.0296, 88.3629) -> (25.9044, 88.3521)
    line L1477 (26.1507, 88.3809) -> (26.0296, 88.3629)
    line L1478 (26.2678, 88.4061) -> (26.1507, 88.3809)
    line L1479 (26.3808, 88.4384) -> (26.2678, 88.4061)
    line L1480 (26.4898, 88.478) -> (26.3808, 88.4384)
    line L1481 (26.5948, 88.5247) -> (26.4898, 88.478)
    line L1482 (26.6957, 88.5786) -> (26.5948, 88.5247)
    line L1483 (26.7926, 88.6398) -> (26.6957, 88.5786)
    line L1484 (26.8854, 88.7081) -> (26.7926, 88.6398)
    line L1485 (26.9734, 88.7832) -> (26.8854, 88.7081)
    line L1486 (27.0559, 88.8649) -> (26.9734, 88.7832)
    line L1487 (27.1327, 88.9531) -> (27.0559, 88.8649)
    line L1488 (27.204, 89.0478) -> (27.1327, 88.9531)
    line L1489 (27.2697, 89.1489) -> (27.204, 89.0478)
    line L1490 (27.3298, 89.2566) -> (27.2697, 89.1489)
    line L1491 (27.3843, 89.3708) -> (27.3298, 89.2566)
    line L1492 (27.4332, 89.4915) -> (27.3843, 89.3708)
    line L1493 (27.4765, 89.6187) -> (27.4332, 89.4915)
    line L1494 (27.5143, 89.7524) -> (27.4765, 89.6187)
    line L1495 (26.9585, 89.8927) -> (27.5143, 89.7524)
    line L1496 (21.7872, 88.4202) -> (21.2314, 88.4202)
    line L1497 (21.7872, 90.1993) -> (21.7872, 88.4202)
    line L1498 (23.4632, 92.6202) -> (21.7872, 90.1993)
    line L1499 (22.8157, 92.6202) -> (23.4632, 92.6202)
    line L1500 (22.0021, 91.3854) -> (22.8157, 92.6202)
    line L1501 (21.949, 91.3037) -> (22.0021, 91.3854)
    line L1502 (21.8976, 91.2237) -> (21.949, 91.3037)
    line L1503 (21.8477, 91.1453) -> (21.8976, 91.2237)
    line L1504 (21.7995, 91.0686) -> (21.8477, 91.1453)
    line L1505 (21.7529, 90.9936) -> (21.7995, 91.0686)
    line L1506 (21.7078, 90.9202) -> (21.7529, 90.9936)
    line L1507 (21.6644, 90.8485) -> (21.7078, 90.9202)
    line L1508 (21.6226, 90.7785) -> (21.6644, 90.8485)
    line L1509 (21.5823, 90.7101) -> (21.6226, 90.7785)
    line L1510 (21.5437, 90.6434) -> (21.5823, 90.7101)
    line L1511 (21.5039, 90.7144) -> (21.5437, 90.6434)
    line L1512 (21.4634, 90.7855) -> (21.5039, 90.7144)
    line L1513 (21.4223, 90.8565) -> (21.4634, 90.7855)
    line L1514 (21.3805, 90.9275) -> (21.4223, 90.8565)
    line L1515 (21.3382, 90.9986) -> (21.3805, 90.9275)
    line L1516 (21.2952, 91.0696) -> (21.3382, 90.9986)
    line L1517 (21.2515, 91.1407) -> (21.2952, 91.0696)
    line L1518 (21.2073, 91.2117) -> (21.2515, 91.1407)
    line L1519 (21.1624, 91.2828) -> (21.2073, 91.2117)
    line L1520 (21.1168, 91.3539) -> (21.1624, 91.2828)
    line L1521 (20.2889, 92.6202) -> (21.1168, 91.3539)
    line L1522 (19.6128, 92.6202) -> (20.2889, 92.6202)
    line L1523 (21.2314, 90.1993) -> (19.6128, 92.6202)
    line L1524 (21.2314, 88.4202) -> (21.2314, 90.1993)
    line L1525 (19.3864, 88.4202) -> (16.7621, 88.4202)
    line L1526 (19.3864, 88.9158) -> (19.3864, 88.4202)
    line L1527 (17.3179, 88.9158) -> (19.3864, 88.9158)
    line L1528 (17.3179, 92.6202) -> (17.3179, 88.9158)
    line L1529 (16.7621, 92.6202) -> (17.3179, 92.6202)
    line L1530 (16.7621, 88.4202) -> (16.7621, 92.6202)
    line L1531 (48.3035, 78.0146) -> (48.3035, 85.0296)
    line L1532 (50.2698, 78.0146) -> (48.3035, 78.0146)
    line L1533 (50.2698, 85.0296) -> (50.2698, 78.0146)
    line L1534 (52.648, 85.0296) -> (50.2698, 85.0296)
    line L1535 (52.648, 86.6771) -> (52.648, 85.0296)
    line L1536 (45.9253, 86.6771) -> (52.648, 86.6771)
    line L1537 (45.9253, 85.0296) -> (45.9253, 86.6771)
    line L1538 (48.3035, 85.0296) -> (45.9253, 85.0296)
    line L1539 (41.2232, 77.8583) -> (41.0493, 77.8551)
    line L1540 (41.3939, 77.8677) -> (41.2232, 77.8583)
    line L1541 (41.5617, 77.8832) -> (41.3939, 77.8677)
    line L1542 (41.7264, 77.9051) -> (41.5617, 77.8832)
    line L1543 (41.888, 77.9332) -> (41.7264, 77.9051)
    line L1544 (42.0466, 77.9676) -> (41.888, 77.9332)
    line L1545 (42.2021, 78.0081) -> (42.0466, 77.9676)
    line L1546 (42.3545, 78.055) -> (42.2021, 78.0081)
    line L1547 (42.5039, 78.1081) -> (42.3545, 78.055)
    line L1548 (42.6503, 78.1674) -> (42.5039, 78.1081)
    line L1549 (42.793, 78.2325) -> (42.6503, 78.1674)
    line L1550 (42.9317, 78.3032) -> (42.793, 78.2325)
    line L1551 (43.0662, 78.3792) -> (42.9317, 78.3032)
    line L1552 (43.1966, 78.4608) -> (43.0662, 78.3792)
    line L1553 (43.3229, 78.5477) -> (43.1966, 78.4608)
    line L1554 (43.445, 78.6401) -> (43.3229, 78.5477)
    line L1555 (43.5631, 78.738) -> (43.445, 78.6401)
    line L1556 (43.677, 78.8412) -> (43.5631, 78.738)
    line L1557 (43.7868, 78.95) -> (43.677, 78.8412)
    line L1558 (43.8925, 79.0642) -> (43.7868, 78.95)
    line L1559 (43.9938, 79.1836) -> (43.8925, 79.0642)
    line L1560 (44.0905, 79.3081) -> (43.9938, 79.1836)
    line L1561 (44.1825, 79.4377) -> (44.0905, 79.3081)
    line L1562 (44.2698, 79.5722) -> (44.1825, 79.4377)
    line L1563 (44.3526, 79.7119) -> (44.2698, 79.5722)
    line L1564 (44.4306, 79.8566) -> (44.3526, 79.7119)
    line L1565 (44.504, 80.0063) -> (44.4306, 79.8566)
    line L1566 (44.5728, 80.1611) -> (44.504, 80.0063)
    line L1567 (44.6369, 80.3209) -> (44.5728, 80.1611)
    line L1568 (44.6963, 80.4858) -> (44.6369, 80.3209)
    line L1569 (44.7506, 80.6555) -> (44.6963, 80.4858)
    line L1570 (44.7992, 80.8296) -> (44.7506, 80.6555)
    line L1571 (44.842, 81.0083) -> (44.7992, 80.8296)
    line L1572 (44.8792, 81.1915) -> (44.842, 81.0083)
    line L1573 (44.9106, 81.3793) -> (44.8792, 81.1915)
    line L1574 (44.9363, 81.5715) -> (44.9106, 81.3793)
    line L1575 (44.9563, 81.7683) -> (44.9363, 81.5715)
    line L1576 (44.9705, 81.9696) -> (44.9563, 81.7683)
    line L1577 (44.9791, 82.1754) -> (44.9705, 81.9696)
    line L1578 (44.982, 82.3857) -> (44.9791, 82.1754)
    line L1579 (44.9791, 82.5934) -> (44.982, 82.3857)
    line L1580 (44.9705, 82.7968) -> (44.9791, 82.5934)
    line L1581 (44.9563, 82.9957) -> (44.9705, 82.7968)
    line L1582 (44.9363, 83.1903) -> (44.9563, 82.9957)
    line L1583 (44.9106, 83.3805) -> (44.9363, 83.1903)
    line L1584 (44.8792, 83.5663) -> (44.9106, 83.3805)
    line L1585 (44.842, 83.7477) -> (44.8792, 83.5663)
    line L1586 (44.7992, 83.9247) -> (44.842, 83.7477)
    line L1587 (44.7506, 84.0974) -> (44.7992, 83.9247)
    line L1588 (44.6963, 84.2657) -> (44.7506, 84.0974)
    line L1589 (44.6369, 84.4292) -> (44.6963, 84.2657)
    line L1590 (44.5728, 84.5875) -> (44.6369, 84.4292)
    line L1591 (44.504, 84.7406) -> (44.5728, 84.5875)
    line L1592 (44.4306, 84.8885) -> (44.504, 84.7406)
    line L1593 (44.3526, 85.0313) -> (44.4306, 84.8885)
    line L1594 (44.2698, 85.1688) -> (44.3526, 85.0313)
    line L1595 (44.1825, 85.3013) -> (44.2698, 85.1688)
    line L1596 (44.0905, 85.4284) -> (44.1825, 85.3013)
    line L1597 (43.9938, 85.5505) -> (44.0905, 85.4284)
    line L1598 (43.8925, 85.6674) -> (43.9938, 85.5505)
    line L1599 (43.7868, 85.7789) -> (43.8925, 85.6674)
    line L1600 (43.677, 85.885) -> (43.7868, 85.7789)
    line L1601 (43.5631, 85.9856) -> (43.677, 85.885)
    line L1602 (43.445, 86.0808) -> (43.5631, 85.9856)
    line L1603 (43.3229, 86.1705) -> (43.445, 86.0808)
    line L1604 (43.1966, 86.2549) -> (43.3229, 86.1705)
    line L1605 (43.0662, 86.3337) -> (43.1966, 86.2549)
    line L1606 (42.9317, 86.4071) -> (43.0662, 86.3337)
    line L1607 (42.793, 86.4751) -> (42.9317, 86.4071)
    line L1608 (42.6503, 86.5376) -> (42.793, 86.4751)
    line L1609 (42.5039, 86.5944) -> (42.6503, 86.5376)
    line L1610 (42.3545, 86.6452) -> (42.5039, 86.5944)
    line L1611 (42.2021, 86.69) -> (42.3545, 86.6452)
    line L1612 (42.0466, 86.7289) -> (42.2021, 86.69)
    line L1613 (41.888, 86.7618) -> (42.0466, 86.7289)
    line L1614 (41.7264, 86.7887) -> (41.888, 86.7618)
    line L1615 (41.5617, 86.8096) -> (41.7264, 86.7887)
    line L1616 (41.3939, 86.8246) -> (41.5617, 86.8096)
    line L1617 (41.2232, 86.8335) -> (41.3939, 86.8246)
    line L1618 (41.0493, 86.8365) -> (41.2232, 86.8335)
    line L1619 (40.8755, 86.8335) -> (41.0493, 86.8365)
    line L1620 (40.7047, 86.8246) -> (40.8755, 86.8335)
    line L1621 (40.5369, 86.8096) -> (40.7047, 86.8246)
    line L1622 (40.3722, 86.7887) -> (40.5369, 86.8096)
    line L1623 (40.2106, 86.7618) -> (40.3722, 86.7887)
    line L1624 (40.0521, 86.7289) -> (40.2106, 86.7618)
    line L1625 (39.8965, 86.69) -> (40.0521, 86.7289)
    line L1626 (39.7441, 86.6452) -> (39.8965, 86.69)
    line L1627 (39.5947, 86.5944) -> (39.7441, 86.6452)
    line L1628 (39.4483, 86.5376) -> (39.5947, 86.5944)
    line L1629 (39.3056, 86.4752) -> (39.4483, 86.5376)
    line L1630 (39.167, 86.4074) -> (39.3056, 86.4752)
    line L1631 (39.0324, 86.3343) -> (39.167, 86.4074)
    line L1632 (38.902, 86.2559) -> (39.0324, 86.3343)
    line L1633 (38.7757, 86.1722) -> (38.902, 86.2559)
    line L1634 (38.6536, 86.0832) -> (38.7757, 86.1722)
    line L1635 (38.5355, 85.9889) -> (38.6536, 86.0832)
    line L1636 (38.4216, 85.8892) -> (38.5355, 85.9889)
    line L1637 (38.3118, 85.7843) -> (38.4216, 85.8892)
    line L1638 (38.2061, 85.674) -> (38.3118, 85.7843)
    line L1639 (38.1048, 85.5584) -> (38.2061, 85.674)
    line L1640 (38.0081, 85.4375) -> (38.1048, 85.5584)
    line L1641 (37.9161, 85.3113) -> (38.0081, 85.4375)
    line L1642 (37.8288, 85.1798) -> (37.9161, 85.3113)
    line L1643 (37.7461, 85.0429) -> (37.8288, 85.1798)
    line L1644 (37.668, 84.9008) -> (37.7461, 85.0429)
    line L1645 (37.5946, 84.7533) -> (37.668, 84.9008)
    line L1646 (37.5258, 84.6005) -> (37.5946, 84.7533)
    line L1647 (37.4618, 84.4424) -> (37.5258, 84.6005)
    line L1648 (37.4023, 84.2789) -> (37.4618, 84.4424)
    line L1649 (37.348, 84.1105) -> (37.4023, 84.2789)
    line L1650 (37.2995, 83.9375) -> (37.348, 84.1105)
    line L1651 (37.2566, 83.7598) -> (37.2995, 83.9375)
    line L1652 (37.2195, 83.5775) -> (37.2566, 83.7598)
    line L1653 (37.188, 83.3905) -> (37.2195, 83.5775)
    line L1654 (37.1624, 83.1988) -> (37.188, 83.3905)
    line L1655 (37.1424, 83.0025) -> (37.1624, 83.1988)
    line L1656 (37.128, 82.8016) -> (37.1424, 83.0025)
    line L1657 (37.1195, 82.596) -> (37.128, 82.8016)
    line L1658 (37.1166, 82.3857) -> (37.1195, 82.596)
    line L1659 (37.1195, 82.1754) -> (37.1166, 82.3857)
    line L1660 (37.128, 81.9696) -> (37.1195, 82.1754)
    line L1661 (37.1424, 81.7683) -> (37.128, 81.9696)
    line L1662 (37.1624, 81.5715) -> (37.1424, 81.7683)
    line L1663 (37.188, 81.3793) -> (37.1624, 81.5715)
    line L1664 (37.2195, 81.1915) -> (37.188, 81.3793)
    line L1665 (37.2566, 81.0083) -> (37.2195, 81.1915)
    line L1666 (37.2995, 80.8296) -> (37.2566, 81.0083)
    line L1667 (37.348, 80.6555) -> (37.2995, 80.8296)
    line L1668 (37.4023, 80.4858) -> (37.348, 80.6555)
    line L1669 (37.4618, 80.3209) -> (37.4023, 80.4858)
    line L1670 (37.5258, 80.1611) -> (37.4618, 80.3209)
    line L1671 (37.5946, 80.0063) -> (37.5258, 80.1611)
    line L1672 (37.668, 79.8566) -> (37.5946, 80.0063)
    line L1673 (37.7461, 79.7119) -> (37.668, 79.8566)
    line L1674 (37.8288, 79.5722) -> (37.7461, 79.7119)
    line L1675 (37.9161, 79.4377) -> (37.8288, 79.5722)
    line L1676 (38.0081, 79.3081) -> (37.9161, 79.4377)
    line L1677 (38.1048, 79.1836) -> (38.0081, 79.3081)
    line L1678 (38.2061, 79.0642) -> (38.1048, 79.1836)
    line L1679 (38.3118, 78.95) -> (38.2061, 79.0642)
    line L1680 (38.4216, 78.8412) -> (38.3118, 78.95)
    line L1681 (38.5355, 78.738) -> (38.4216, 78.8412)
    line L1682 (38.6536, 78.6401) -> (38.5355, 78.738)
    line L1683 (38.7757, 78.5477) -> (38.6536, 78.6401)
    line L1684 (38.902, 78.4608) -> (38.7757, 78.5477)
    line L1685 (39.0324, 78.3792) -> (38.902, 78.4608)
    line L1686 (39.167, 78.3032) -> (39.0324, 78.3792)
    line L1687 (39.3056, 78.2325) -> (39.167, 78.3032)
    line L1688 (39.4483, 78.1674) -> (39.3056, 78.2325)
    line L1689 (39.5947, 78.1081) -> (39.4483, 78.1674)
    line L1690 (39.7441, 78.055) -> (39.5947, 78.1081)
    line L1691 (39.8965, 78.0081) -> (39.7441, 78.055)
    line L1692 (40.0521, 77.9676) -> (39.8965, 78.0081)
    line L1693 (40.2106, 77.9332) -> (40.0521, 77.9676)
